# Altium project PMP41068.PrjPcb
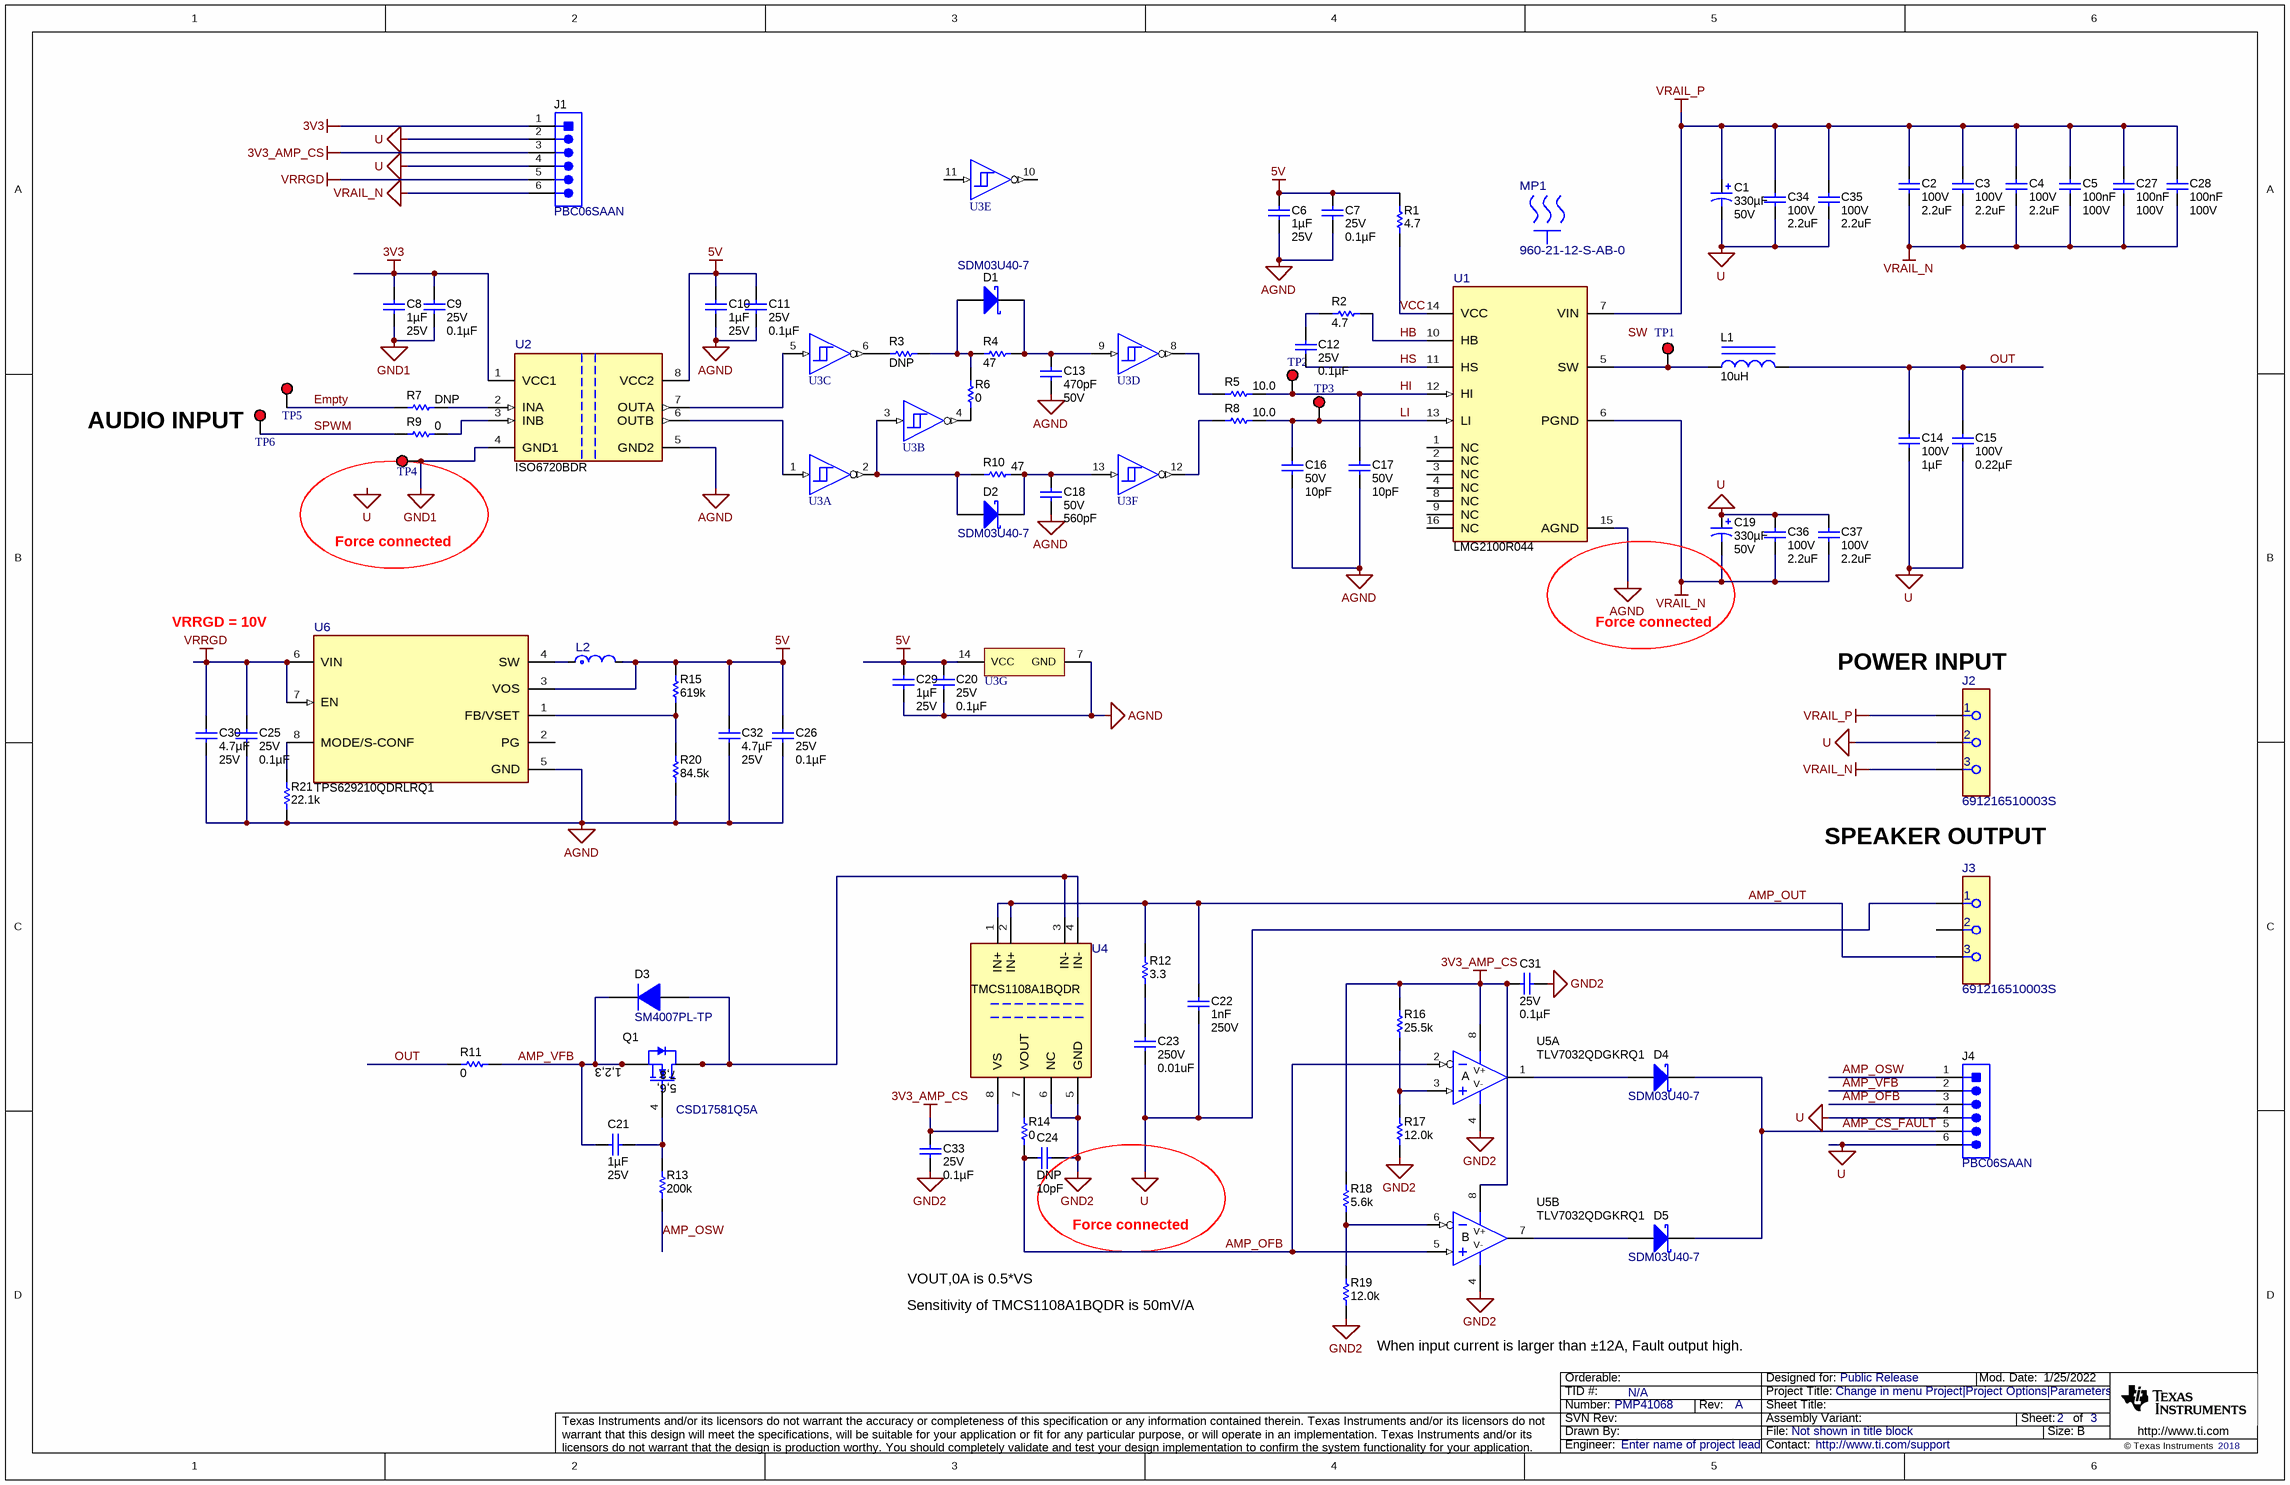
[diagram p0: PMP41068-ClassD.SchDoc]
CopyrightYear: 2018; PCB_Layout: Who did the Layout?; PCB_Rev: A; PRJ_Customer: Public Release; PRJ_Engineer: Enter name of project lead; PRJ_Number: PMP41068; PRJ_Title: Change in menu Project|Project Options|Parameters; SCH_Rev: A; TechSupport: http://www.ti.com/support; TID: N/A
1 sheet, 83 parts. Net scope: global (net labels, ports and power ports of the same name join across sheets).
Board file: PMP41068.PcbDoc

## Sheet PMP41068-ClassD.SchDoc
size 431 x 279 mm; Date: Not shown in title block; ApprovedBy: Not shown in title block; CheckedBy: Not shown in title block; Author: Not shown in title block; CompanyName: Not shown in title block; Engineer: Not shown in title block; Organization: Not shown in title block; Address1: Not shown in title block; Address2: Not shown in title block; Address3: Not shown in title block; Address4: Not shown in title block; DocumentNumber: 2; Revision: Use project parameter SCH_Rev; SheetNumber: 2; SheetTotal: 3; PageSetup: Record=PageOptions¦CenterHorizontal=True¦CenterVertical=True¦PrintScale=1.00¦XCorrection=1.00¦YCorrection=1.00¦PrintKind=0¦BorderSize=5000000¦LeftOffset=0¦BottomOffset=0¦Orientation=2¦PaperLength=1000¦PaperWidth=1000¦Scale=100¦PaperSource=15¦PrintQuality=600¦MediaType=1¦DitherType=10¦PaperKind=Letter¦PrintScaleMode=1

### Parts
C1  ValueDisplayed: 330µF  VDC_V: 50V  [SM_RADIAL_G]  (hidden comment: EEE-FT1H331AP)
C2  VDC_V: 100V  ValueDisplayed: 2.2uF  [1206_180]  (hidden comment: CGA5L3X7S2A225K160AB)
C3  VDC_V: 100V  ValueDisplayed: 2.2uF  [1206_180]  (hidden comment: CGA5L3X7S2A225K160AB)
C4  VDC_V: 100V  ValueDisplayed: 2.2uF  [1206_180]  (hidden comment: CGA5L3X7S2A225K160AB)
C5  Cap_F: 100nF  VDC_V: 100V  [0603]  (hidden comment: GCJ188R72A104KA01D)
C6  Cap_F: 1µF  VDC_V: 25V  [0603]  (hidden comment: GCM188R71E105KA64D)
C7  VDC_V: 25V  ValueDisplayed: 0.1µF  [0402]  (hidden comment: CGA2B3X7R1E104K050BB)
C8  Cap_F: 1µF  VDC_V: 25V  [0603]  (hidden comment: GCM188R71E105KA64D)
C9  VDC_V: 25V  ValueDisplayed: 0.1µF  [0402]  (hidden comment: CGA2B3X7R1E104K050BB)
C10  Cap_F: 1µF  VDC_V: 25V  [0603]  (hidden comment: GCM188R71E105KA64D)
C11  VDC_V: 25V  ValueDisplayed: 0.1µF  [0402]  (hidden comment: CGA2B3X7R1E104K050BB)
C12  VDC_V: 25V  ValueDisplayed: 0.1µF  [0402]  (hidden comment: CGA2B3X7R1E104K050BB)
C13  Cap_F: 470pF  VDC_V: 50V  [0402]  (hidden comment: GRT1555C1H471JA02D)
C14  VDC_V: 100V  ValueDisplayed: 1µF  [1206]  (hidden comment: GCJ31CR72A105KA01K)
C15  VDC_V: 100V  ValueDisplayed: 0.22µF  [0603]  (hidden comment: HMK107C7224MAHTE)
C16  VDC_V: 50V  ValueDisplayed: 10pF  [0402]  (hidden comment: GCM1555C1H100JA16D)
C17  VDC_V: 50V  ValueDisplayed: 10pF  [0402]  (hidden comment: GCM1555C1H100JA16D)
C18  VDC_V: 50V  ValueDisplayed: 560pF  [0402]  (hidden comment: GRM1555C1H561JA01D)
C19  ValueDisplayed: 330µF  VDC_V: 50V  [SM_RADIAL_G]  (hidden comment: EEE-FT1H331AP)
C20  VDC_V: 25V  ValueDisplayed: 0.1µF  [0402]  (hidden comment: CGA2B3X7R1E104K050BB)
C21  Cap_F: 1µF  VDC_V: 25V  [0603]  (hidden comment: GCM188R71E105KA64D)
C22  Cap_F: 1nF  VDC_V: 250V  [0805_HV]  (hidden comment: GRM21AR72E102KW01D)
C23  VDC_V: 250V  ValueDisplayed: 0.01uF  [0805_HV]  (hidden comment: CGA4J3C0G2E103J125AA)
C24  VDC_V: DNP  ValueDisplayed: 10pF  [0402]  (hidden comment: GCM1555C1H100JA16D)
C25  VDC_V: 25V  ValueDisplayed: 0.1µF  [0402]  (hidden comment: CGA2B3X7R1E104K050BB)
C26  VDC_V: 25V  ValueDisplayed: 0.1µF  [0402]  (hidden comment: CGA2B3X7R1E104K050BB)
C27  Cap_F: 100nF  VDC_V: 100V  [0603]  (hidden comment: GCJ188R72A104KA01D)
C28  Cap_F: 100nF  VDC_V: 100V  [0603]  (hidden comment: GCJ188R72A104KA01D)
C29  Cap_F: 1µF  VDC_V: 25V  [0603]  (hidden comment: GCM188R71E105KA64D)
C30  Cap_F: 4.7µF  VDC_V: 25V  [0805L]  (hidden comment: CGA4J1X7R1E475K125AC)
C31  VDC_V: 25V  ValueDisplayed: 0.1µF  [0402]  (hidden comment: CGA2B3X7R1E104K050BB)
C32  Cap_F: 4.7µF  VDC_V: 25V  [0805L]  (hidden comment: CGA4J1X7R1E475K125AC)
C33  VDC_V: 25V  ValueDisplayed: 0.1µF  [0402]  (hidden comment: CGA2B3X7R1E104K050BB)
C34  VDC_V: 100V  ValueDisplayed: 2.2uF  [1206_180]  (hidden comment: CGA5L3X7S2A225K160AB)
C35  VDC_V: 100V  ValueDisplayed: 2.2uF  [1206_180]  (hidden comment: CGA5L3X7S2A225K160AB)
C36  VDC_V: 100V  ValueDisplayed: 2.2uF  [1206_180]  (hidden comment: CGA5L3X7S2A225K160AB)
C37  VDC_V: 100V  ValueDisplayed: 2.2uF  [1206_180]  (hidden comment: CGA5L3X7S2A225K160AB)
D1  SDM03U40-7  [SOD-523]
D2  SDM03U40-7  [SOD-523]
D3  SM4007PL-TP  [SOD-123FL]
D4  SDM03U40-7  [SOD-523]
D5  SDM03U40-7  [SOD-523]
J1  PBC06SAAN  [Sullins_PxC06SAAN]
J2  691216510003S  [FP-691216510003S_CONN_TERM_BLOCK3-MFG]
J3  691216510003S  [FP-691216510003S_CONN_TERM_BLOCK3-MFG]
J4  PBC06SAAN  [Sullins_PxC06SAAN]
L1  ValueDisplayed: 10uH  [PA4344]  (hidden comment: PA4344.103NLT)
L2  XGL3530-332MEC  [FP-XGL3530_SMT_IND_3MM2_3MM5-MFG]  (value not drawn)
MP1  960-21-12-S-AB-0  [FP-960-21-12-S-AB-0_HEATSINK_BGA_21MM_12MM-MFG]
Q1  CSD17581Q5A  [DQJ0008A]
R1  ValueDisplayed: 4.7  [0402]  (hidden comment: CRCW04024R70JNED)
R2  ValueDisplayed: 4.7  [0402]  (hidden comment: CRCW04024R70JNED)
R3  ValueDisplayed: DNP  [0402]  (hidden comment: CRCW04020000Z0ED)
R4  ValueDisplayed: 47  [0402]  (hidden comment: CRCW040247R0JNED)
R5  ValueDisplayed: 10.0  [0402]  (hidden comment: RMCF0402JT10R0)
R6  ValueDisplayed: 0  [0402]  (hidden comment: CRCW04020000Z0ED)
R7  ValueDisplayed: DNP  [0402]  (hidden comment: CRCW04020000Z0ED)
R8  ValueDisplayed: 10.0  [0402]  (hidden comment: RMCF0402JT10R0)
R9  ValueDisplayed: 0  [0402]  (hidden comment: CRCW04020000Z0ED)
R10  ValueDisplayed: 47  [0402]  (hidden comment: CRCW040247R0JNED)
R11  ValueDisplayed: 0  [2512]  (hidden comment: CRCW25120000Z0EGHP)
R12  ValueDisplayed: 3.3  [0805_HV]  (hidden comment: CRCW08053R30JNEA)
R13  ValueDisplayed: 200k  [0603]  (hidden comment: CRCW0603200KFKEA)
R14  ValueDisplayed: 0  [0402]  (hidden comment: CRCW04020000Z0ED)
R15  ValueDisplayed: 619k  [0402]  (hidden comment: CRCW0402619KFKED)
R16  ValueDisplayed: 25.5k  [0402]  (hidden comment: CRCW040225K5FKED)
R17  ValueDisplayed: 12.0k  [0402]  (hidden comment: CRCW040212K0FKED)
R18  ValueDisplayed: 5.6k  [0402]  (hidden comment: CRCW04025K60JNED)
R19  ValueDisplayed: 12.0k  [0402]  (hidden comment: CRCW040212K0FKED)
R20  ValueDisplayed: 84.5k  [0402]  (hidden comment: CRCW040284K5FKED)
R21  ValueDisplayed: 22.1k  [0402]  (hidden comment: CRCW040222K1FKED)
TP1  5000  [Keystone5000]  (value not drawn)
TP2  5000  [Keystone5000]  (value not drawn)
TP3  5000  [Keystone5000]  (value not drawn)
TP4  5000  [Keystone5000]  (value not drawn)
TP5  5000  [Keystone5000]  (value not drawn)
TP6  5000  [Keystone5000]  (value not drawn)
U1  LMG2100R044  [RAR0016A-MFG]
U2  ISO6720BDR  [D0008A-MFG]
U3  SN74AC14NSR  [NS0014A_M]  (value not drawn)  (parts A,B,C,D,E,F,G of 7)
U4  TMCS1108A1BQDR  [D0008A-MFG]
U5  TLV7032QDGKRQ1  [DGK0008A_N]  (parts A,B of 2)
U6  TPS629210QDRLRQ1  [DRL0008A-MFG]

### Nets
3V3: C8.1 C9.1 J1.1 U2.1(VCC1)
3V3_AMP_CS: C31.1 C33.1 J1.3 R16.2 R18.2 U4.8(VS) U5.8(V+)
5V: C6.1 C7.1 C10.1 C11.1 C20.1 C26.1 C29.1 C32.1 L2.2 R1.2 R15.2 U2.8(VCC2) U3.14(VCC) U6.3(VOS)
AGND: C6.2 C7.2 C10.2 C11.2 C13.2 C16.2 C17.2 C18.2 C20.2 C25.2 C26.2 C29.2 C30.2 C32.2 R20.1 R21.1 U1.15(AGND) U2.5(GND2) U3.7(GND) U6.5(GND)
GND1: C8.2 C9.2 TP4.1 U2.4(GND1)
GND2: C24.2 C31.2 C33.2 R17.1 R19.1 U4.5(GND) U4.6(NC) U5.4(V-)
U: C1.2(-) C14.2 C15.2 C19.1(+) C22.2 C23.2 C34.2 C35.2 C36.1 C37.1 J1.2 J1.4 J2.2 J3.1 J4.4 J4.6
VRAIL_N: C2.2 C3.2 C4.2 C5.2 C19.2(-) C27.2 C28.2 C36.2 C37.2 J1.6 J2.3 U1.6(PGND)
VRAIL_P: C1.1(+) C2.1 C3.1 C4.1 C5.1 C27.1 C28.1 C34.1 C35.1 J2.1 U1.7(VIN)
VRRGD: C25.1 C30.1 J1.5 U6.6(VIN) U6.7(EN)
AMP_CS_FAULT: D4.1(K) D5.1(K) J4.5
AMP_OFB: C24.1 J4.3 R14.1 U5.2(IN-) U5.5(IN+)
AMP_OSW: J4.1 R13.1
AMP_OUT: C22.1 J3.3 R12.2 U4.1(IN+) U4.2(IN+)
AMP_VFB: C21.1 D3.1(K) J4.2 Q1.1(S) Q1.2(S) Q1.3(S) R11.2
Empty: R7.1 TP5.1
HB: R2.1 U1.10(HB)
HI: C17.1 R5.2 TP2.1 U1.12(HI)
HS: C12.2 U1.11(HS)
LI: C16.1 R8.2 TP3.1 U1.13(LI)
OUT: C14.1 C15.1 L1.2 R11.1
SPWM: R9.1 TP6.1
VCC: R1.1 U1.14(VCC)
NetC12_1: C12.1 R2.2
NetC13_1: C13.1 D1.1(K) R4.2 U3.9(4A)
NetC18_1: C18.1 D2.1(K) R10.2 U3.13(6A)
NetC21_2: C21.2 Q1.4(G) R13.2
NetC23_1: C23.1 R12.1
NetD1_2: D1.2(A) R3.2 R4.1 R6.2
NetD2_2: D2.2(A) R10.1 U3.2(~{1Y}) U3.3(2A)
NetD3_2: D3.2(A) Q1.5(D) Q1.6(D) Q1.7(D) Q1.8(D) Q1.9(D) U4.3(IN-) U4.4(IN-)
NetD4_2: D4.2(A) U5.1(OUT)
NetD5_2: D5.2(A) U5.7(OUT)
NetL1_1: L1.1 TP1.1 U1.5(SW)
NetL2_1: L2.1 U6.4(SW)
NetR3_1: R3.1 U3.6(~{3Y})
NetR5_1: R5.1 U3.8(~{4Y})
NetR6_1: R6.1 U3.4(~{2Y})
NetR7_2: R7.2 U2.2(INA)
NetR8_1: R8.1 U3.12(~{6Y})
NetR9_2: R9.2 U2.3(INB)
NetR14_2: R14.2 U4.7(VOUT)
NetR15_1: R15.1 R20.2 U6.1(FB/VSET)
NetR16_1: R16.1 R17.2 U5.3(IN+)
NetR18_1: R18.1 R19.2 U5.6(IN-)
NetR21_2: R21.2 U6.8(MODE/S-CONF)
NetU2_6: U2.6(OUTB) U3.1(1A)
NetU2_7: U2.7(OUTA) U3.5(3A)

Not connected (* = marked no-connect by the designer): J3 2; U1 1(NC) 2(NC) 3(NC) 4(NC) 8(NC) 9(NC) 16(NC); U3 10(~{5Y}) 11(5A); U6 2(PG)

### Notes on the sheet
- (near TP6) AUDIO INPUT
- Force connected
- VRRGD = 10V
- (near J2) POWER INPUT
- SPEAKER OUTPUT
- VOUT,0A is 0.5*VS
- Sensitivity of TMCS1108A1BQDR is 50mV/A
- (near R19) When input current is larger than ±12A, Fault output high.
- Labels drawn without touching a wire or pin: SW, U

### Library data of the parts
C1 C19 = CMP-0860442-1: CAP, AL, 330 µF, 50 V, +/- 20%, 0.12 ohm, AEC-Q200 Grade 2, SMD; Manufacturer: Panasonic; ESR_ohm: 0.12; CompType: Capacitor; U/M: EA; AEC Qualified: Y; TaMax_C: 105°C; Green_Lifecycle: Active; SizeY_mm: 10.3; SizeZ_mm: 10.2; Value: 330uF; AEC Grade: 2; TaMin_C: -55°C; Green_REACh: Passed; SizeArea_mm2: 123.6; AEC Category: Q200; Cap_Case: 10x10.2mm; SizeAreaWB_mm2: 172.2; SizeX_mm: 12
C2-C4 C34-C37 = CMP-0008790-2: CAP, CERM, 2.2 uF, 100 V, +/- 10%, X7S, AEC-Q200 Grade 1, 1206; Manufacturer: TDK; TaMin_C: -55°C; ESR_ohm: 5.718m; Polarized: N; SizeAreaWB_mm2: 10.92; Value1: 0.005718 ohm; U/M: EA; Value: 2.2uF; TaMax_C: 125°C; SizeZ_mm: 1.8; SizeX_mm: 3.2; SizeY_mm: 1.6; SizeArea_mm2: 5.12; AEC Qualified: Y; Cap_F: 2.2µF; IRMS_A: 3.03632A; AEC Grade: 1; AEC Category: Q200
C5 C27 C28 = CMP-0064935-2: CAP, CERM, 0.1 uF, 100 V,+/- 10%, X7R, AEC-Q200 Grade 1, 0603; Manufacturer: MuRata; TaMin_C: -55°C; Polarized: N; SizeAreaWB_mm2: 4.68; Value1: Unknown; U/M: EA; Value: 0.1uF; TaMax_C: 125°C; SizeZ_mm: 1; SizeX_mm: 1.6; SizeY_mm: 0.8; SizeArea_mm2: 1.28; AEC Qualified: Y; AEC Category: Q200
C6 C8 C10 C21 C29 = CMP-0007139-1: CAP, CERM, 1 uF, 25 V, +/- 10%, X7R, AEC-Q200 Grade 1, 0603; Manufacturer: MuRata; TaMin_C: -55°C; Polarized: N; SizeAreaWB_mm2: 4.68; Value1: Unknown; U/M: EA; Value: 1uF; TaMax_C: 125°C; SizeZ_mm: 1; SizeX_mm: 1.6; SizeY_mm: 0.8; SizeArea_mm2: 1.28; AEC Qualified: Y; AEC Category: Q200
C7 C9 C11 C12 C20 C25 C26 C31 C33 = CMP-0080610-1: CAP, CERM, 0.1 µF, 25 V,+/- 10%, X7R, AEC-Q200 Grade 1, 0402; Manufacturer: TDK; TaMin_C: -55°C; Polarized: N; SizeAreaWB_mm2: 3; U/M: EA; Value: 0.1uF; TaMax_C: 125°C; SizeZ_mm: 0.6; SizeX_mm: 1; SizeY_mm: 0.5; AEC Qualified: Y; Cap_F: 100nF; AEC Category: Q200
C13 = CMP-0860800-1: CAP, CERM, 470 pF, 50 V,+/- 5%, C0G, AEC-Q200 Grade 1, 0402; Manufacturer: MuRata; U/M: EA; Polarized: N; AEC Category: Q200; SizeY_mm: 0.5; SizeAreaWB_mm2: 3; AEC Qualified: Y; TaMax_C: 125°C; Value: 470pF; SizeX_mm: 1; TaMin_C: -55°C; SizeZ_mm: 0.6
C14 = CMP-0750040-1: CAP, CERM, 1 µF, 100 V,+/- 10%, X7R, AEC-Q200 Grade 1, 1206; Manufacturer: MuRata; Value: 1uF; U/M: EA; SizeX_mm: 3.2; Polarized: N; TaMin_C: -55°C; SizeZ_mm: 1.35; SizeY_mm: 1.6; AEC Category: Q200; SizeArea_mm2: 5.12; TaMax_C: 125°C; AEC Grade: 1; AEC Qualified: Y; SizeAreaWB_mm2: 10.92
C15 = CMP-0077895-2: CAP, CERM, 0.22 µF, 100 V,+/- 20%, X7S, AEC-Q200 Grade 1, 0603; Manufacturer: Taiyo Yuden; TaMin_C: -55°C; Polarized: N; SizeAreaWB_mm2: 4.68; U/M: EA; Value: 0.22uF; TaMax_C: 125°C; SizeZ_mm: 1.0; SizeX_mm: 1.6; SizeY_mm: 0.8; SizeArea_mm2: 1.28; AEC Qualified: Y; Cap_F: 220nF; AEC Grade: 1; AEC Category: Q200
C16 C17 = CMP-0860290-1: CAP, CERM, 10 pF, 50 V,+/- 5%, C0G/NP0, AEC-Q200 Grade 1, 0402; Manufacturer: MuRata; TaMin_C: -55°C; AEC Grade: 1; AEC Qualified: Y; SizeAreaWB_mm2: 3; SizeZ_mm: 0.6; Value: 10pF; TaMax_C: 125°C; Polarized: N; SizeArea_mm2: 0.5; U/M: EA; AEC Category: Q200
C18 = CMP-0006479-2: CAP, CERM, 560 pF, 50 V, +/- 5%, C0G/NP0, 0402; Manufacturer: MuRata; TaMin_C: -55°C; Polarized: N; SizeAreaWB_mm2: 3; Value1: Unknown; U/M: EA; Value: 560pF; TaMax_C: 125°C; SizeZ_mm: 0.6; SizeX_mm: 1; SizeY_mm: 0.5; AEC Category: Q200
C22 = CMP-0008251-2: CAP, CERM, 1000 pF, 250 V, +/- 10%, X7R, 0805; Manufacturer: MuRata; TaMin_C: -55°C; Polarized: N; SizeAreaWB_mm2: 6.75; Value1: Unknown; U/M: EA; Value: 1000pF; TaMax_C: 125°C; SizeZ_mm: 1.45; SizeX_mm: 2; SizeY_mm: 1.25; Cap_Case: 0805; SizeArea_mm2: 2.5; AEC Category: Q200
C23 = CMP-0007972-1: CAP, CERM, 0.01 uF, 250 V, +/- 5%, C0G/NP0, AEC-Q200 Grade 1, 0805; Manufacturer: TDK; TaMin_C: -55°C; Polarized: N; SizeAreaWB_mm2: 6.75; Value1: Unknown; U/M: EA; Value: 0.01uF; TaMax_C: 125°C; SizeZ_mm: 1.45; SizeX_mm: 2; SizeY_mm: 1.25; Cap_Case: 0805; SizeArea_mm2: 2.5; AEC Qualified: Y; Cap_F: 10nF; AEC Grade: 1; AEC Category: Q200
C24 = CMP-0860290-1: CAP, CERM, 10 pF, 50 V,+/- 5%, C0G/NP0, AEC-Q200 Grade 1, 0402; Manufacturer: MuRata; TaMin_C: -55°C; AEC Grade: 1; AEC Qualified: Y; SizeAreaWB_mm2: 3; SizeZ_mm: 0.6; Value: 10pF; TaMax_C: 125°C; Polarized: N; Value2: 50V; SizeArea_mm2: 0.5; U/M: EA; AEC Category: Q200
C30 C32 = CMP-0076706-1: CAP, CERM, 4.7 µF, 25 V,+/- 10%, X7R, AEC-Q200 Grade 1, 0805; Manufacturer: TDK; SizeAreaWB_mm2: 6.75; SizeArea_mm2: 2.5; AEC Qualified: Y; AEC Category: Q200; Value: 4.7uF; TaMax_C: 125°C; SizeZ_mm: 1.45; AEC Grade: 1; Polarized: N; TaMin_C: -55°C; SizeY_mm: 1.25; U/M: EA; SizeX_mm: 2.0; Cap_Case: 2x1.25x1.25mm
D1 D2 D4 D5 = CMP-0028563-1: Diode, Schottky, 40 V, 0.03 A, SOD-523; Manufacturer: Diodes Inc.; Io_A: 30mA; Green_Lifecycle: Active; SizeAreaWB_mm2: 5.13; Vr_V: 40V; Green_REACh: Passed; Value1: 0.03A; TJmax_C: 125°C; U/M: EA; Value: 40V; SizeZ_mm: 0.65; SizeX_mm: 1.7; SizeY_mm: 0.9; Vf_V: 1V; SizeArea_mm2: 1.53; AEC Category: Q101
D3 = CMP-0077021-2: Diode, Standard Recovery Rectifier, 1000 V, 1 A, SOD-123FL; Manufacturer: Micro Commercial Components; SizeAreaWB_mm2: 12.19; Value: 1000V; Vr_V: 1kV; Io_A: 1A; SizeX_mm: 3.6; SizeArea_mm2: 5.94; SizeZ_mm: 0.98; Green_Lifecycle: Not Set; Green_REACh: Incomplete; TJmax_C: 175°C; AEC Category: Q101; Vf_V: 1.1V; SizeY_mm: 1.65
J1 J4 = CMP-0054603-1: Header, 2.54mm, 6x1, Gold, TH; Manufacturer: Sullins Connector Solutions; CNHeader: TRUE; Current_A: 3A; Green_Lifecycle: Not Set; Shrouded: N; Gender: Male; Green_REACh: Incomplete; Row_Count: 1; Pitch_mm: 2.54; CT: FALSE; Cert_UL: Y
J2 J3 = CMP-0096886-1: Manufacturer: Wurth Electronics; ContactFinish: Tin,Nickel; DUT-Pitch_mm: 5.08mm; Conn Orientation: Horizontal; SizeZ_mm: 13.9mm; Max Wire Gauge: 12; Voltage_V: 300V; Conn Gender: Female; Min Wire Gauge: 30; AEC Qualified: No; Is Female: yes; Current_A: 14A; Row_Count: 1
L1 = CMP-0062096-1: Inductor, Shielded, 10 uH, 16.5 A, 0.013 ohm, AEC-Q200 Grade 1, SMD; Manufacturer: Pulse Engineering; Isat: 24A @ 30% inductance drop; Irms: 16.5A @ 40C rise; Green_Lifecycle: Not Set; SizeAreaWB_mm2: 378.24; DCR_ohm: 0.013; Green_REACh: Incomplete; Value: 10uH; Imax_A: 16.5A; SizeZ_mm: 7; SizeX_mm: 17.7; SizeY_mm: 17.2; SizeArea_mm2: 304.44; Ind_H: 10µH; AEC Qualified: Y; AEC Grade: 1; AEC Category: Q200
L2 = CMP-0092762-2: Power Inductor, shielded, composite, 20% tol, SMT, RoHS, halogen-free   USD 0.580; Manufacturer: Coilcraft; Ind_H: 3.3µH; Value: 3.3uH; Self Resonant Frequency: 43MHz; TaMax_C: +125°C; TaMin_C: -40°C; AEC Qualified: Yes; Isat: 1.6A; DCR_ohm: 0.0374; SizeZ_mm: 3mm; Irms: 5.4A; Test Frequency: 1MHz; Shrouded: true; AEC Grade: Grade 1
MP1 = CMP-0090374-1: HEATSINK 21X12MM SIDE PLASTIC PUSH PIN; Manufacturer: Wakefield-Vette; Mating Package: BGA; SizeZ_mm: 12mm; AEC Qualified: No
Q1 = CMP-0071234-1: MOSFET, N-CH, 30 V, 24 A, DQJ0008A (VSONP-8); Alternate Manufacturer: None; Manufacturer: Texas Instruments; Rdson45_ohm: 4.2m; QgTyp_nC: 20.0; SizeAreaWB_mm2: 55.2; Vgs_V: 20V; Value1: 0.0042 ohm; VdsMax_V: 30V; U/M: EA; Value: 30V; IdsMax_A: 24A; SizeZ_mm: 1.1; SizeX_mm: 6.0; SizeY_mm: 4.9; Value2: 20 nC; SizeArea_mm2: 29.4; ChType: N; AEC Category: Q101
R1 R2 = CMP-0026942-3: RES, 4.7, 5%, 0.063 W, AEC-Q200 Grade 0, 0402; Manufacturer: Vishay-Dale; Power_W: 63mW; TempCo: 200 ppm/C; Value_Code: 4R70; Value: 4.7; EIA_Code: E24; SizeX_mm: 1; SizeY_mm: 0.5; SizeZ_mm: 0.6; Value2: 0.063W; AEC Qualified: Y; VDC_V: 50V; AEC Category: Q200; AEC Grade: 0
R3 R6 R7 R9 R14 = CMP-0026822-3: RES, 0, 5%, 0.063 W, AEC-Q200 Grade 0, 0402; Manufacturer: Vishay-Dale; Power_W: 63mW; TempCo: 200 ppm/C; Value_Code: 0000; Value: 0; EIA_Code: E24; SizeX_mm: 1; SizeY_mm: 0.5; SizeZ_mm: 0.6; Value2: 0.063W; AEC Qualified: Y; VDC_V: 50V; AEC Category: Q200
R4 R10 = CMP-0026936-3: RES, 47, 5%, 0.063 W, AEC-Q200 Grade 0, 0402; Manufacturer: Vishay-Dale; Power_W: 63mW; TempCo: 200 ppm/C; Value_Code: 47R0; Value: 47; EIA_Code: E24; SizeX_mm: 1; SizeY_mm: 0.5; SizeZ_mm: 0.6; Value2: 0.063W; AEC Qualified: Y; VDC_V: 50V; AEC Category: Q200; AEC Grade: 0
R5 R8 = CMP-0026764-1: RES, 10.0, 1%, 0.063 W, AEC-Q200 Grade 0, 0402; Manufacturer: Stackpole Electronics Inc; Power_W: 63mW; TempCo: 100 ppm/C; Value_Code: 10R0; U/M: EA; Value: 10.0; EIA_Code: E96; Res_ohm: 10; SizeX_mm: 1; SizeY_mm: 0.5; SizeZ_mm: 0.6; Value2: 0.063W; AEC Qualified: Y; AEC Grade: 0; AEC Category: Q200
R11 = CMP-0015865-2: RES, 0, 5%, 1.5 W, AEC-Q200 Grade 0, 2512; Manufacturer: Vishay-Dale; Power_W: 1.5W; TempCo: ppm/C; Value_Code: 0000; U/M: EA; Value: 0; EIA_Code: E24; SizeX_mm: 6.3; SizeY_mm: 3.2; SizeZ_mm: 0.71; SizeArea_mm2: 20.16; AEC Qualified: Y; AEC Category: Q200
R12 = CMP-0020547-3: RES, 3.3, 5%, 0.125 W, AEC-Q200 Grade 0, 0805; Manufacturer: Vishay-Dale; Power_W: 125mW; TempCo: 200 ppm/C; Value_Code: 3R30; Value: 3.3; EIA_Code: E24; SizeX_mm: 2; SizeY_mm: 1.25; SizeZ_mm: 1.45; Value2: 0.125W; SizeArea_mm2: 2.5; AEC Qualified: Y; VDC_V: 150V; AEC Category: Q200; AEC Grade: 0
R13 = CMP-0022200-4: RES, 200 k, 1%, 0.1 W, AEC-Q200 Grade 0, 0603; Manufacturer: Vishay-Dale; Power_W: 100mW; TempCo: 100 ppm/C; Value: 200k; EIA_Code: E96; SizeX_mm: 1.6; SizeY_mm: 0.8; SizeZ_mm: 1; Value2: 0.1W; SizeArea_mm2: 1.28; AEC Qualified: Y; VDC_V: 75V; AEC Category: Q200; AEC Grade: 0
R15 = CMP-0026488-2: RES, 619 k, 1%, 0.063 W, AEC-Q200 Grade 0, 0402; Manufacturer: Vishay-Dale; Power_W: 63mW; TempCo: 100 ppm/C; Value: 619k; EIA_Code: E96; SizeX_mm: 1; SizeY_mm: 0.5; SizeZ_mm: 0.6; Value2: 0.063W; AEC Qualified: Y; VDC_V: 50V; AEC Category: Q200; AEC Grade: 0
R16 = CMP-0026201-2: RES, 25.5 k, 1%, 0.063 W, AEC-Q200 Grade 0, 0402; Manufacturer: Vishay-Dale; Power_W: 63mW; TempCo: 100 ppm/C; Value_Code: 25k5; Value: 25.5k; EIA_Code: E96; SizeX_mm: 1; SizeY_mm: 0.5; SizeZ_mm: 0.6; Value2: 0.063W; AEC Qualified: Y; VDC_V: 50V; AEC Category: Q200; AEC Grade: 0
R17 R19 = CMP-0025990-3: RES, 12.0 k, 1%, 0.063 W, AEC-Q200 Grade 0, 0402; Manufacturer: Vishay-Dale; Power_W: 63mW; TempCo: 100 ppm/C; Value_Code: 12k0; Value: 12.0k; Res_ohm: 12k; SizeX_mm: 1; SizeY_mm: 0.5; SizeZ_mm: 0.6; Value2: 0.063W; AEC Qualified: Y; VDC_V: 50V; AEC Grade: 0; AEC Category: Q200
R18 = CMP-0026952-5: RES, 5.6 k, 5%, 0.063 W, AEC-Q200 Grade 0, 0402; Manufacturer: Vishay-Dale; Power_W: 63mW; TempCo: 200 ppm/C; Value_Code: 5k60; Value: 5.6k; EIA_Code: E24; SizeX_mm: 1; SizeY_mm: 0.5; SizeZ_mm: 0.6; Value2: 0.063W; AEC Qualified: Y; VDC_V: 50V; AEC Category: Q200; AEC Grade: 0
R20 = CMP-0026578-2: RES, 84.5 k, 1%, 0.063 W, AEC-Q200 Grade 0, 0402; Manufacturer: Vishay-Dale; Power_W: 63mW; TempCo: 100 ppm/C; Value_Code: 84k5; Value: 84.5k; EIA_Code: E96; SizeX_mm: 1; SizeY_mm: 0.5; SizeZ_mm: 0.6; Value2: 0.063W; AEC Qualified: Y; VDC_V: 50V; AEC Category: Q200; AEC Grade: 0
R21 = CMP-0026178-2: RES, 22.1 k, 1%, 0.063 W, AEC-Q200 Grade 0, 0402; Manufacturer: Vishay-Dale; Power_W: 63mW; TempCo: 100 ppm/C; Value_Code: 22k1; Value: 22.1k; EIA_Code: E96; SizeX_mm: 1; SizeY_mm: 0.5; SizeZ_mm: 0.6; Value2: 0.063W; AEC Qualified: Y; VDC_V: 50V; AEC Category: Q200; AEC Grade: 0
TP1-TP6 = CMP-0055137-2: Test Point, Miniature, Red, TH; Manufacturer: Keystone Electronics; Green_REACh: Passed; Green_Lifecycle: Active; ContactFinish: Silver; CNHeader: FALSE; CT: TRUE
U1 = CMP-0097820-2: Manufacturer: Texas Instruments; AEC Category: Q200; CompType: IC; Standoff Height: 0mm; SizeZ_mm: 0.89mm
U2 = CMP-0095064-1: Manufacturer: Texas Instruments; AEC Qualified: No; TaMax_C: +125°C; Standoff Height: 0.11mm; TaMin_C: -40°C; Max Supply Voltage: 5.5V; TJmax_C: +150°C; SizeZ_mm: 1.75mm; Min Supply Voltage: 1.71V
U3 = CMP-0045831-1: Hex Schmitt-Trigger Inverters, NS0014A, LARGE T&R; Manufacturer: Texas Instruments; tpd @ Nom Voltage(Max)(ns): 15,11; VCC(Min)(V): 2; F @ Nom Voltage(Max)(Mhz): 100; ICC @ Nom Voltage(Max)(mA): 0.02; Technology Family: AC; Input Type: CMOS; Output Drive (IOL/IOH)(Max)(mA): -24/24; Schmitt Trigger: Yes; Rating: Catalog; VCC(Max)(V): 6; Voltage(Nom)(V): 3.3,5
U4 = CMP-0090388-1: Basic Isolation Hall-Effect Current Sensor; Manufacturer: Texas Instruments; Standoff Height: 0.11mm; SizeZ_mm: 1.75mm; Sensor Output: Analog Voltage; Sensing Method: Hall Effect; Current Sensitivity: 50mV/A
U5 = CMP-0860105-1: Small Size, Nanopower, Low-Voltage Comparators, DGK0008A (VSSOP-8); Alternate PartNumber: TLV7032DGKT; Alternate Manufacturer: Texas Instruments; AEC Category: Q200; SizeY_mm: 3; CompType: IC; SizeX_mm: 4.9; SizeAreaWB_mm2: 23.6; AEC Qualified: N; SizeArea_mm2: 14.7; SizeZ_mm: 1.1
U6 = CMP-0089687-1: 3-V to 17-V, Synchronous Buck Converters in 1.6 mm x 2.1 mm SOT583 Package; Manufacturer: Texas Instruments; AEC Qualified: Yes; Standoff Height: 0mm; Output Voltage: 0.4-5.5V; Nominal Supply Current: 8mA; SizeZ_mm: 0.6mm; Number Of Outputs: 1; TJmax_C: +150°C; Output Type: AdjustableProgrammable; Max Supply Voltage: 17V; Min Supply Voltage: 3V; Switching Frequency: 2.5MHz

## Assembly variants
001: not fitted FID1 FID2 FID3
